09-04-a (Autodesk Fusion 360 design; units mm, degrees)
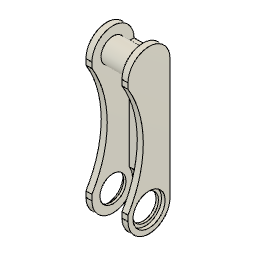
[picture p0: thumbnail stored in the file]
sketch "スケッチ1" plane through (0, 0, 0) normal (1, 0, 0) x axis (0, 0, -1)
  circle C1 centre (0, 40) radius 4
  point P1 (0, 0)
  point P2 (0, 40)
  vertical P1 P2
  dimension "d1" diameter C1 = 8
  dimension "d29" distance P1 P2 = 40
extrude "押し出し1" new body sketch "スケッチ1" + "スケッチ5" profile of S1:C1 distance 10
sketch "スケッチ2" plane through (5, 0, 0) normal (1, 0, 0) x axis (0, 0, -1)
  line L1 (-7, 0) -> (-7, 40)
  line L2 (7, 40) -> (7, 0)
  line L3 (0, 0) -> (0, 40)
  circle C1 centre (0, 40) radius 4
  arc A1 centre (0, 0) radius 7 clockwise from (7, 0) to (-7, 0)
  arc A2 centre (0, 40) radius 7 clockwise from (-7, 40) to (7, 40)
  point P7 (0, 40)
  point P9 (0, 40)
  point P8 (0, 0)
  tangent L1 A1
  tangent A1 L2
  parallel L1 L2
  tangent L2 A2
  tangent L1 A2
  vertical L3
  coincident P7 P9
  concentric C1 A2
  dimension "d4" radius A2 = 7
  dimension "d5" distance P7 P8 = 40
extrude "押し出し2" add sketch "スケッチ2" profile of C1 L1 A1 L2 A2 along normal blind 2
mirror "ミラー" sketch "スケッチ5" mirrorStitchTolerance 0.1
sketch "スケッチ3" plane through (0, 0, 0) normal (1, 0, 0) x axis (0, 0, -1)
  line L1 (7, 40) -> (5.4, 40)
  line L2 (7, 0) -> (7, 40)
  line L3 (5.4, 0) -> (7, 0)
  line L4 (5.4, 40) -> (5.4, 0)
  point P3 (7, 40)
  point P6 (7, 40)
  point P4 (7, 0)
  point P7 (7, 0)
  horizontal L1
  vertical L2
  horizontal L3
  vertical L4
  coincident P3 P6
  coincident P4 P7
  dimension "d10" distance L2 L4 = 1.6
extrude "押し出し3" add sketch "スケッチ3" distance 10
sketch "スケッチ4" plane through (0, 0, 0) normal (1, 0, 0) x axis (0, 0, -1)
  circle C1 centre (-36.9324, 20) radius 35
  arc A1 centre (0, 40) radius 7 clockwise from (-7, 40) to (7, 40)
  arc A2 centre (0, 0) radius 7 clockwise from (7, 0) to (-7, 0)
  tangent C1 A1
  tangent C1 A2
  dimension "d13" diameter C1 = 70
extrude "押し出し4" cut sketch "スケッチ4" profile of C1 no distance stored
sketch "スケッチ5" plane through (0, 0, 0) normal (1, 0, 0) x axis (0, 0, -1)
  circle C1 centre (0, 0) radius 6.5
  arc A1 centre (0, 0) radius 7 clockwise from (7, 0) to (-7, 0)
  concentric C1 A1
  dimension "d15" diameter C1 = 13
extrude "押し出し5" cut sketch "スケッチ5" profile of C1 distance 10
chamfer "面取り" distance 0.2
hole "穴1" HoleDepth 2 HoleDiameter 8.7 TipAngle 118 CBDepth 1.2 CBDiameter 10.7
hole "穴2" HoleDepth 2 HoleDiameter 8.7 TipAngle 118 CBDepth 1.2 CBDiameter 10.7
